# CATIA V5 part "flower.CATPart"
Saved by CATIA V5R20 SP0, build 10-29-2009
Part number: flower
Material "Water": density 1000 kg/m3
Material "Multicoloured Flag"
Material "Brass": density 8216 kg/m3, Young's modulus 1.31e+11 Pa, Poisson ratio 0.35, thermal expansion 1.67e-05 1/K
Bounding box of the stored display mesh (mm): x -45.563 to 45.563, y -45.563 to 61.991, z 0 to 139.66
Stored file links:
  C:\Users\ysz\Desktop\新建文件夹\flower.CATPart
  D:\CATIAR20\win_b64\startup\materials\Catalog.CATMaterial
  D:\CATIAR20\win_b64\startup\materials\teak_2.jpg
  D:\CATIAR20\win_b64\startup\materials\cedar.jpg
  D:\CATIAR20\win_b64\startup\materials\blue_env_512x512.jpg
  D:\CATIAR20\win_b64\startup\materials\DS_star.jpg
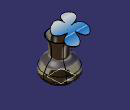
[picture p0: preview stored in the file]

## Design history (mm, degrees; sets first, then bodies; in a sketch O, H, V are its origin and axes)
Body1 (main body), material "Brass"
  Plane1: type Offset, RefPlane xy-plane, Offset 20
  Plane2: type Offset, RefPlane Plane1, Offset 20
  Plane3: type Offset, RefPlane Plane2, Offset 20
  Plane4: type Offset, RefPlane Plane3, Offset 20
  Plane5: type Offset, RefPlane Plane4, Offset 20
  Sketch1 on Plane5, origin (0, 0, 100), H (1, 0, 0), V (0, 1, 0)
    circle A1 centre (0, 0) radius 29.8266
  Sketch2 on Plane4, origin (0, 0, 80), H (1, 0, 0), V (0, 1, 0)
    circle A1 centre (0, 0) radius 23.0726
  Sketch3 on Plane3, origin (0, 0, 60), H (1, 0, 0), V (0, 1, 0)
    circle A1 centre (0, 0) radius 21.9749
  Sketch4 on Plane2, origin (0, 0, 40), H (1, 0, 0), V (0, 1, 0)
    circle A1 centre (0, 0) radius 37.8812
  Sketch5 on Plane1, origin (0, 0, 20), H (1, 0, 0), V (0, 1, 0)
    circle A1 centre (0, 0) radius 45.607
  Sketch6 on xy-plane, origin (0, 0, 0), H (1, 0, 0), V (0, 1, 0)
    circle A1 centre (0, 0) radius 31.6229
  Loft1: solid, Sections (Sketch1; Sketch2; Sketch3; Sketch4; Sketch5; Sketch6)
  Shell1: IntOffset 1, Face face of Loft1, ExtOffset 0
Body2, material "Water"
  Sketch7 on yz-plane, origin (0, 0, 0), H (0, 1, 0), V (0, 0, 1)
    axis line L1 (0, 117.0904) -> (0, -14.88)
    point P1 (0, 117.0904)
    line L2 (0, 0) -> (30.5626, 0)
    line L3 (30.5626, 0) -> (41.5502, 9.897)
    line L4 (41.5502, 9.897) -> (44.4279, 15.6349)
    line L5 (44.4279, 15.6349) -> (44.4279, 21.6335)
    line L6 (44.4279, 21.6335) -> (43.1199, 28.9362)
    line L7 (43.1199, 28.9362) -> (0, 28.9362)
    point P8 (0, 28.9362)
    line L8 (0, 28.9362) -> (0, 0)
    coincidence: P1 V, P8 L1
    vertical: L1 V, L5 V, L8 V
    horizontal: L2 H, L7 H
  Shaft1: profile Sketch7, axis Sketch7.L1, angle 360
Body3, material "Multicoloured Flag"
  Sketch8 on yz-plane, origin (0, 0, 0), H (0, 1, 0), V (0, 0, 1)
    spline S1 through (4.925, 3.3767) (15.651, 101.1809) (24.5457, 125.9579)
    point P1 (24.5457, 125.9579)
    point P2 (24.5457, 125.9579)
    coincidence: P1 P2
  Plane6: type Normal, Curve Sketch8, RefPoint vertex of Sketch8
  Sketch9 on Plane6, origin (0, -0.2087, 3.0221), H (-1, 0, 0), V (0, 0.9976, 0.0689)
    circle A1 centre (0, 4.9123) radius 1
    point P1 (0, 4.9123)
    radius A1 = 1
    coincidence: P1 V
  Rib1: profile Sketch9, centre curve Sketch8
  Plane7: type OffsetPt, RefPlane zx-plane, RefPoint Sketch8.P2
  Plane8: type Normal, Curve Sketch8, RefPoint Sketch8.P2
  Sketch10 on Plane8, origin (0, 48.2205, 116.1272), H (1, 0, 0), V (0, -0.9235, 0.3835)
    spline S1 through (-4.3423, 41.7545) (-19.2273, 61.1433) (-37.8855, 41.7545) (-12.0228, 30.6751) (-40.4521, 21.5134) (-23.8706, -3.9187) (-8.5786, 13.9217) (2.1878, -12.1777) (28.996, 6.7624) (7.7842, 19.0587) (34.5873, 27.8468) (18.1132, 54.0973) (-4.3423, 41.7545)
    point P1 (-4.3423, 41.7545)
    point P2 (-4.3423, 41.7545)
    coincidence: P1 P2
  Pad1: profile Sketch10, direction (0, -0.3835, -0.9235), length 1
